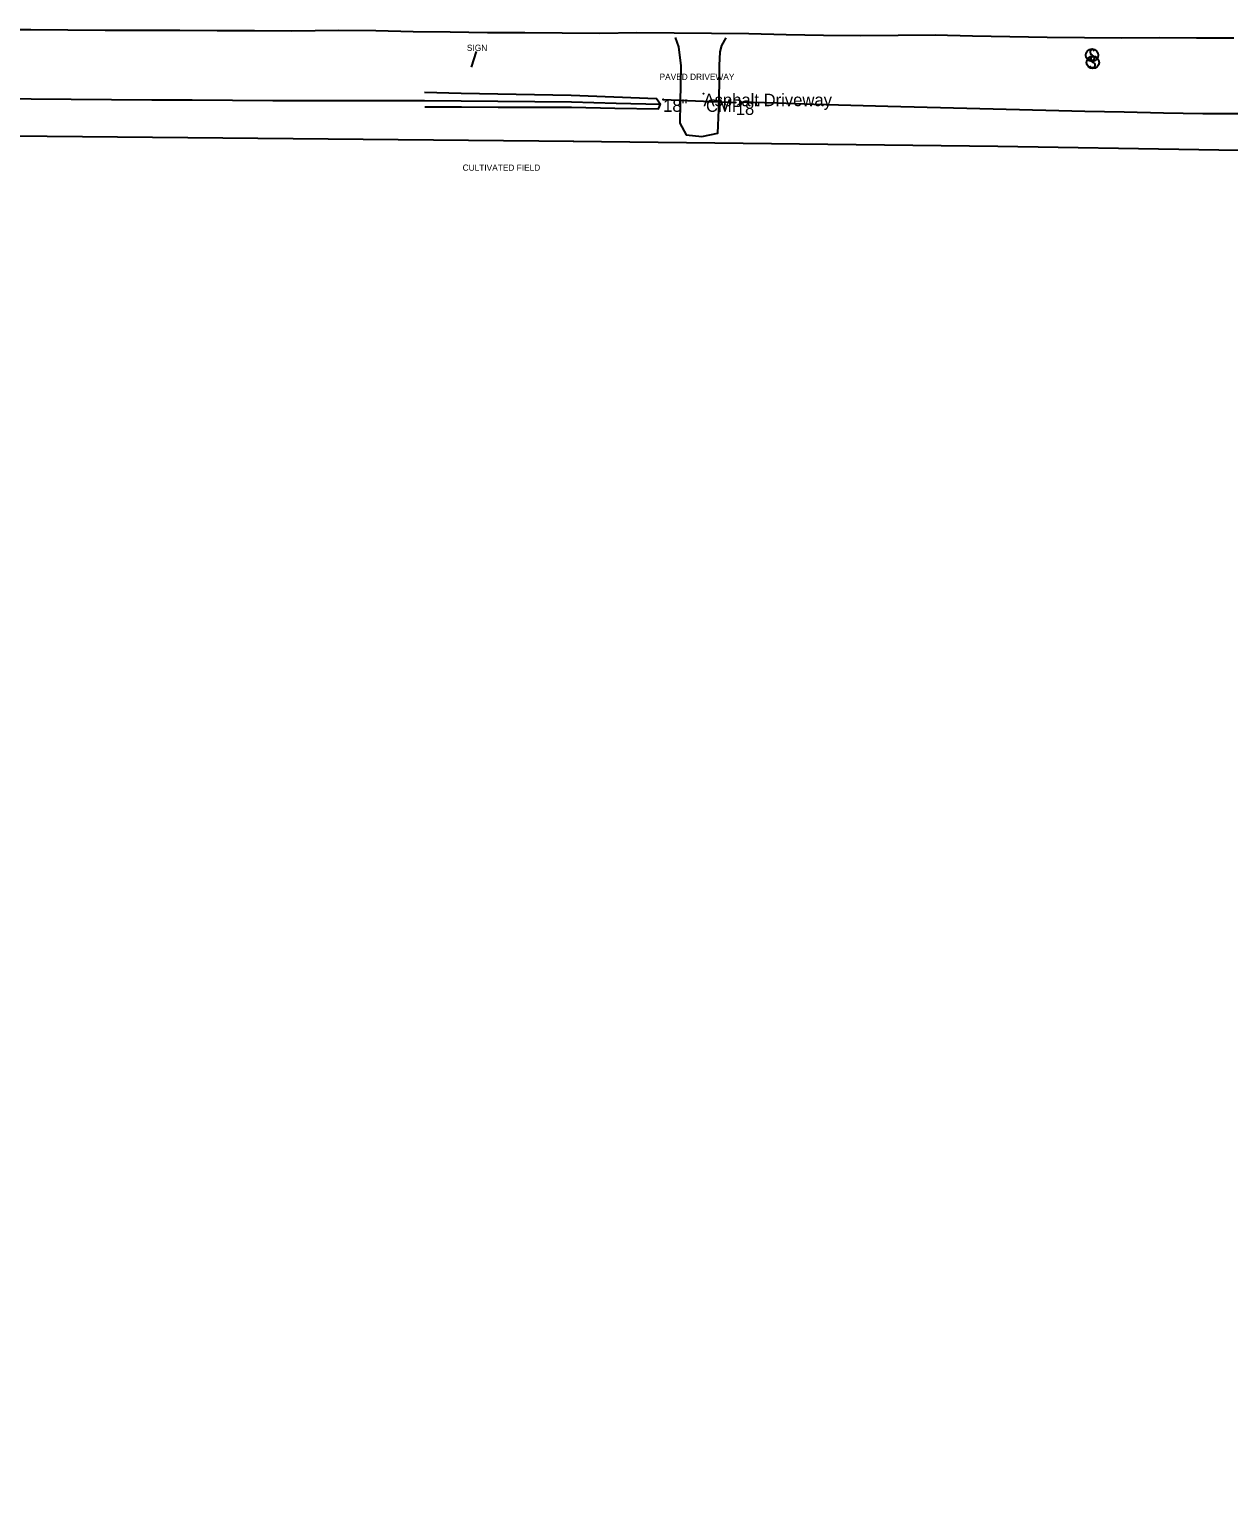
# Model space of a CAD drawing. Extents: x 1802180 to 1804859, y 572524 to 575172.
# Drawn here: x 1802662 to 1803144, y 573185 to 573780 of the extents above; entities that cross this region are included whole.
import ezdxf

# ---------------------------------------------------------------- set-up
doc = ezdxf.new("R2010")
doc.units = 0
for name, color, linetype in [('EX_SHOULDER', 7, 'Continuous'), ('S_DITCHLINE', 7, 'Continuous'), ('S_DRG_PT_SYM', 7, 'Continuous'), ('S_DRIVEWAY', 7, 'Continuous'), ('S_DRIVEWAY_ANNOT', 7, 'Continuous'), ('S_MISC_BOUNDARY', 7, 'Continuous'), ('S_MISC_BOUNDARY_ANNOT', 7, 'Continuous'), ('S_MSC_PT_SYM', 7, 'Continuous'), ('S_SIDE_DRAIN', 7, 'Continuous'), ('S_SIDE_DRAIN_ANNOT', 7, 'Continuous'), ('S_SIGN', 7, 'Continuous'), ('S_SIGN_ANNOT', 7, 'Continuous'), ('S_SURVEY_TEXT_ANNOT', 7, 'Continuous')]:
    doc.layers.add(name, color=color, linetype=linetype)

msp = doc.modelspace()

# ---------------------------------------------------------------- linework, layer by layer
at = {"layer": 'EX_SHOULDER'}
for points in [[(1802647.7, 573780.37), (1802662.81, 573780.35), (1802677.75, 573780.24), (1802692.76, 573780.13), (1802707.76, 573780.1), (1802722.76, 573780.08), (1802737.8, 573780.06), (1802752.76, 573779.96), (1802767.76, 573779.86)], [(1802767.76, 573779.86), (1802786.55, 573780.08), (1802801.56, 573779.98), (1802816.56, 573779.6), (1802831.5, 573779.47), (1802846.52, 573779.26), (1802861.52, 573779.16), (1802876.51, 573779.05), (1802891.59, 573778.96), (1802906.55, 573779.17), (1802921.56, 573779.11), (1802936.53, 573778.99), (1802951.53, 573778.76), (1802966.52, 573778.39), (1802981.53, 573778.17), (1802996.53, 573777.98), (1803011.58, 573778.08), (1803026.45, 573778.21), (1803041.54, 573777.82), (1803056.52, 573777.56), (1803071.52, 573777.35), (1803086.52, 573777.21), (1803101.53, 573777.11), (1803116.5, 573777.21), (1803131.53, 573777.1), (1803146.55, 573777.02)]]:
    msp.add_lwpolyline(points, dxfattribs=at)
at = {"layer": 'S_DITCHLINE'}
for points in [[(1802821.2, 573755.17), (1802835.93, 573754.88), (1802850.66, 573754.58), (1802865.39, 573754.29), (1802880.13, 573754), (1802897.28, 573753.32), (1802914.44, 573752.65), (1802916.08, 573750.35)], [(1802646.9, 573752.79), (1802663.01, 573752.61), (1802679.13, 573752.42), (1802695.24, 573752.23), (1802711.49, 573752.16), (1802727.73, 573752.08), (1802743.98, 573752.01), (1802760.22, 573751.93), (1802775.45, 573751.91), (1802790.69, 573751.89), (1802805.92, 573751.87), (1802821.15, 573751.85), (1802835.91, 573751.73), (1802850.68, 573751.61), (1802865.45, 573751.5), (1802880.21, 573751.38), (1802898.15, 573750.86), (1802916.08, 573750.35)], [(1802821.24, 573749.36), (1802835.99, 573749.31), (1802850.75, 573749.26), (1802865.5, 573749.21), (1802880.25, 573749.16), (1802897.71, 573748.83), (1802915.17, 573748.49), (1802916.08, 573750.35)], [(1802947.88, 573751.29), (1802962.76, 573750.88), (1802977.65, 573750.47), (1802992.54, 573750.06), (1803007.43, 573749.65), (1803023.3, 573749.22), (1803039.17, 573748.79), (1803055.04, 573748.36), (1803070.91, 573747.93), (1803086.7, 573747.61), (1803102.49, 573747.29), (1803118.28, 573746.98), (1803134.07, 573746.66), (1803149.62, 573746.68)]]:
    msp.add_lwpolyline(points, dxfattribs=at)
at = {"layer": 'S_DRG_PT_SYM'}
for points in [[(1802917.08, 573752.32), (1802917.08, 573752.37), (1802917.08, 573752.32), (1802917.03, 573752.32), (1802917.08, 573752.32), (1802917.08, 573752.27), (1802917.08, 573752.32), (1802917.13, 573752.32)], [(1802946.29, 573751.09), (1802946.29, 573751.14), (1802946.29, 573751.09), (1802946.24, 573751.09), (1802946.29, 573751.09), (1802946.29, 573751.04), (1802946.29, 573751.09), (1802946.34, 573751.09)]]:
    msp.add_lwpolyline(points, dxfattribs=at)
at = {"layer": 'S_DRIVEWAY'}
msp.add_lwpolyline([(1802921.9, 573777.15), (1802923.24, 573773.38), (1802924.27, 573765.85), (1802923.97, 573751.12), (1802923.81, 573742.78), (1802926.36, 573738.13), (1802932.68, 573737.44), (1802939.09, 573738.72), (1802939.48, 573748.16), (1802939.64, 573753.56), (1802939.69, 573759.09), (1802939.77, 573765.99), (1802939.96, 573771.45), (1802940.66, 573773.94), (1802942.39, 573777.05)], dxfattribs=at)
at = {"layer": 'S_MISC_BOUNDARY'}
for points in [[(1802264.52, 573509.87), (1802267.18, 573599.27), (1802274.19, 573741.25), (1802881.12, 573735.6)], [(1802880.88, 573735.6), (1803051.71, 573733.48), (1803213.27, 573730.83), (1803216.46, 573532.09), (1803301.63, 573530.07), (1803296.75, 573432.28), (1803274.96, 573355.36), (1803226.68, 573219.53), (1803202.19, 573137.5), (1803157.77, 572977.33), (1803158.5, 572726.69), (1802889.88, 572728.1)]]:
    msp.add_lwpolyline(points, dxfattribs=at)
at = {"layer": 'S_MSC_PT_SYM'}
msp.add_lwpolyline([(1802933.32, 573754.6), (1802933.32, 573754.65), (1802933.32, 573754.6), (1802933.27, 573754.6), (1802933.32, 573754.6), (1802933.32, 573754.55), (1802933.32, 573754.6), (1802933.37, 573754.6)], dxfattribs=at)
at = {"layer": 'S_SIDE_DRAIN'}
msp.add_line((1802917.08, 573752.32), (1802946.29, 573751.09), dxfattribs=at)
at = {"layer": 'S_SIGN'}
msp.add_line((1802841.94, 573771.56), (1802839.88, 573765.29), dxfattribs=at)
for centre in [(1803089.55, 573770.1), (1803089.84, 573767.21)]:
    msp.add_circle(centre, 2.5, dxfattribs=at)
for centre, radius, start, end in [((1803089.63, 573771.37), 0.952, 16.52582, 156.89569), ((1803089.4, 573769.27), 1.28, 204.64102, 335.35898), ((1803090.24, 573771.43), 1.51, 167.11961, 241.98129), ((1803090.53, 573768.54), 1.51, 167.11961, 241.98129), ((1803089.91, 573768.48), 0.952, 16.52582, 156.89569), ((1803089.14, 573768.75), 1.4, 358.65289, 73.70634), ((1803089.43, 573765.87), 1.4, 358.65289, 73.70634), ((1803089.69, 573766.39), 1.28, 204.64102, 335.35898)]:
    msp.add_arc(centre, radius, start, end, dxfattribs=at)

# ---------------------------------------------------------------- texts
at = {"layer": 'S_DRIVEWAY_ANNOT'}
msp.add_text('PAVED DRIVEWAY', height=2.5, dxfattribs=at).set_placement((1802915.65, 573760.15))
msp.add_text('PAVED DRIVEWAY', height=2.5, dxfattribs=at).set_placement((1802915.65, 573760.15))
at = {"layer": 'S_MISC_BOUNDARY_ANNOT'}
msp.add_text('CULTIVATED FIELD', height=2.5, dxfattribs=at).set_placement((1802836.47, 573723.65))
at = {"layer": 'S_SIDE_DRAIN_ANNOT'}
for s, p in [('18"    CMP', (1802917.08, 573747.32)), ('18"', (1802946.29, 573746.09))]:
    msp.add_text(s, height=5, dxfattribs=at).set_placement(p)
at = {"layer": 'S_SIGN_ANNOT'}
msp.add_text('SIGN', height=2.5, dxfattribs=at).set_placement((1802838.19, 573771.8))
at = {"layer": 'S_SURVEY_TEXT_ANNOT'}
msp.add_text('Asphalt Driveway', height=5, dxfattribs=at).set_placement((1802933.32, 573749.6))

doc.saveas('drawing.dxf')
